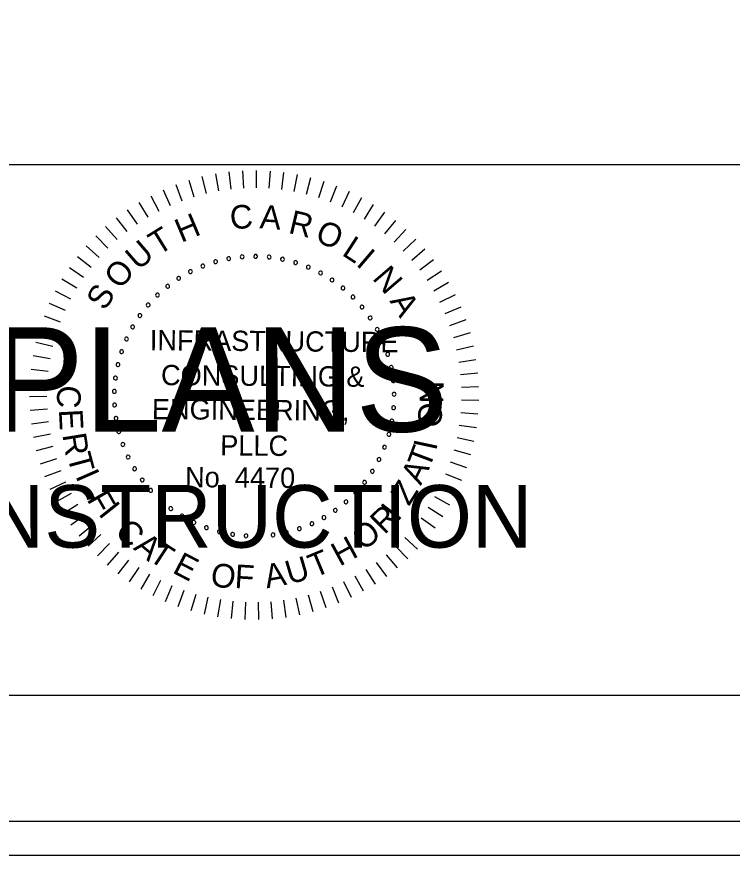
# Model space of a CAD drawing. Extents: x 967 to 1326, y 964 to 2864.
# Drawn here: x 1189.3 to 1212.88, y 963.72 to 991.36 of the extents above; entities that cross this region are included whole.
import ezdxf

# ---------------------------------------------------------------- set-up
doc = ezdxf.new("R2010")
doc.units = 0
for name, color, linetype in [('RD_PD_Final_TX', 7, 'Continuous'), ('RD_XS_TX_Elev_PR', 7, 'Continuous'), ('RD_XS_TX_Misc', 7, 'Continuous'), ('RD_XS_TX_ShdSlope', 7, 'Continuous')]:
    doc.layers.add(name, color=color, linetype=linetype)

msp = doc.modelspace()

# ---------------------------------------------------------------- linework, layer by layer
at = {"layer": 'RD_PD_Final_TX'}
for p, q in [((996.114, 986.486), (1323.886, 986.486)), ((1323.886, 968.983), (996.114, 968.983))]:
    msp.add_line(p, q, dxfattribs=at)
at = {"layer": 'RD_XS_TX_Elev_PR'}
for points in [[(967.409, 963.72), (1326.285, 963.72), (1326.285, 1183.72), (967.409, 1183.72)], [(988.525, 964.84), (1326.285, 964.84), (1326.285, 1182.6), (988.525, 1182.6)]]:
    msp.add_lwpolyline(points, close=True, dxfattribs=at)
at = {"layer": 'RD_XS_TX_ShdSlope'}
for p, q in [((1196.292, 986.245), (1196.357, 985.68)), ((1196.742, 986.282), (1196.772, 985.714)), ((1197.194, 986.292), (1197.189, 985.723)), ((1197.645, 986.274), (1197.606, 985.706)), ((1198.094, 986.228), (1198.02, 985.664)), ((1194.968, 985.971), (1195.134, 985.427)), ((1195.403, 986.09), (1195.536, 985.536)), ((1195.846, 986.181), (1195.945, 985.62)), ((1198.54, 986.156), (1198.432, 985.596)), ((1198.98, 986.056), (1198.838, 985.504)), ((1199.414, 985.929), (1199.238, 985.387)), ((1194.122, 985.656), (1194.353, 985.136)), ((1194.54, 985.827), (1194.739, 985.293)), ((1199.839, 985.777), (1199.63, 985.246)), ((1193.715, 985.461), (1193.978, 984.956)), ((1200.253, 985.598), (1200.013, 985.082)), ((1200.656, 985.395), (1200.385, 984.894)), ((1193.321, 985.241), (1193.614, 984.752)), ((1201.047, 985.167), (1200.745, 984.684)), ((1192.94, 984.997), (1193.263, 984.528)), ((1201.422, 984.917), (1201.092, 984.453)), ((1192.576, 984.731), (1192.926, 984.282)), ((1201.781, 984.643), (1201.424, 984.2)), ((1192.228, 984.443), (1192.605, 984.016)), ((1202.124, 984.349), (1201.739, 983.928)), ((1191.899, 984.134), (1192.301, 983.731)), ((1202.447, 984.034), (1202.038, 983.638)), ((1191.589, 983.805), (1192.015, 983.428)), ((1202.751, 983.7), (1202.318, 983.329)), ((1191.299, 983.459), (1191.748, 983.108)), ((1203.034, 983.348), (1202.579, 983.004)), ((1191.032, 983.095), (1191.501, 982.772)), ((1203.294, 982.979), (1202.82, 982.664)), ((1190.787, 982.716), (1191.274, 982.422)), ((1203.532, 982.595), (1203.04, 982.31)), ((1190.565, 982.323), (1191.07, 982.059)), ((1203.746, 982.198), (1203.237, 981.943)), ((1190.368, 981.916), (1190.888, 981.684)), ((1203.936, 981.788), (1203.412, 981.564)), ((1190.196, 981.499), (1190.729, 981.299)), ((1204.1, 981.367), (1203.563, 981.176)), ((1190.05, 981.072), (1190.594, 980.905)), ((1204.238, 980.937), (1203.691, 980.779)), ((1189.93, 980.636), (1190.484, 980.503)), ((1204.349, 980.5), (1203.794, 980.375)), ((1189.837, 980.195), (1190.398, 980.095)), ((1204.434, 980.056), (1203.872, 979.966)), ((1189.771, 979.748), (1190.337, 979.683)), ((1204.491, 979.608), (1203.925, 979.552)), ((1189.732, 979.298), (1190.301, 979.267)), ((1204.522, 979.158), (1203.953, 979.137)), ((1189.721, 978.847), (1190.29, 978.851)), ((1204.524, 978.706), (1203.955, 978.72)), ((1189.737, 978.396), (1190.306, 978.434)), ((1204.499, 978.256), (1203.932, 978.304)), ((1189.781, 977.946), (1190.346, 978.019)), ((1204.447, 977.807), (1203.884, 977.89)), ((1189.852, 977.5), (1190.412, 977.608)), ((1204.367, 977.363), (1203.81, 977.479)), ((1189.951, 977.06), (1190.502, 977.201)), ((1204.261, 976.924), (1203.712, 977.074)), ((1190.076, 976.626), (1190.617, 976.8)), ((1204.128, 976.492), (1203.589, 976.676)), ((1190.227, 976.2), (1190.757, 976.408)), ((1203.969, 976.07), (1203.442, 976.286)), ((1190.403, 975.785), (1190.92, 976.024)), ((1203.784, 975.658), (1203.271, 975.906)), ((1190.605, 975.381), (1191.106, 975.651)), ((1203.574, 975.258), (1203.078, 975.537)), ((1190.831, 974.99), (1191.315, 975.291)), ((1203.341, 974.871), (1202.862, 975.18)), ((1191.081, 974.614), (1191.545, 974.943)), ((1191.353, 974.253), (1191.796, 974.61)), ((1203.085, 974.5), (1202.626, 974.837)), ((1202.806, 974.145), (1202.368, 974.509)), ((1191.646, 973.91), (1192.067, 974.293)), ((1202.506, 973.807), (1202.092, 974.197)), ((1191.96, 973.585), (1192.356, 973.994)), ((1202.186, 973.488), (1201.796, 973.903)), ((1192.293, 973.28), (1192.664, 973.712)), ((1201.847, 973.19), (1201.484, 973.628)), ((1192.644, 972.996), (1192.988, 973.45)), ((1193.011, 972.734), (1193.327, 973.208)), ((1201.491, 972.912), (1201.155, 973.372)), ((1193.394, 972.495), (1193.68, 972.987)), ((1200.731, 972.425), (1200.453, 972.922)), ((1201.119, 972.657), (1200.811, 973.136)), ((1193.791, 972.279), (1194.047, 972.788)), ((1200.331, 972.217), (1200.083, 972.73)), ((1194.2, 972.088), (1194.424, 972.612)), ((1194.62, 971.923), (1194.812, 972.459)), ((1199.495, 971.877), (1199.312, 972.416)), ((1199.918, 972.034), (1199.702, 972.561)), ((1195.05, 971.783), (1195.208, 972.33)), ((1195.487, 971.67), (1195.612, 972.225)), ((1195.93, 971.584), (1196.021, 972.146)), ((1196.377, 971.524), (1196.434, 972.091)), ((1198.179, 971.562), (1198.097, 972.126)), ((1198.624, 971.64), (1198.508, 972.198)), ((1199.063, 971.745), (1198.913, 972.295)), ((1196.828, 971.493), (1196.85, 972.062)), ((1197.279, 971.488), (1197.267, 972.058)), ((1197.73, 971.512), (1197.683, 972.079))]:
    msp.add_line(p, q, dxfattribs=at)
for centre, start, end in [((1196.285, 983.388), 10.6038, 190.6038), ((1196.727, 983.447), 5.0653, 185.0653), ((1196.727, 983.447), 185.0653, 5.0653), ((1197.172, 983.464), 359.5268, 179.5268), ((1197.172, 983.464), 179.5268, 359.5268), ((1197.617, 983.438), 173.9884, 353.9884), ((1197.617, 983.438), 353.9884, 173.9884), ((1198.057, 983.369), 348.4499, 168.4499), ((1195.429, 983.142), 21.6807, 201.6807), ((1195.429, 983.142), 201.6807, 21.6807), ((1195.851, 983.285), 16.1422, 196.1422), ((1195.851, 983.285), 196.1422, 16.1422), ((1196.285, 983.388), 190.6038, 10.6038), ((1198.057, 983.369), 168.4499, 348.4499), ((1198.489, 983.258), 162.9114, 342.9114), ((1198.489, 983.258), 342.9114, 162.9114), ((1198.908, 983.106), 337.373, 157.373), ((1195.023, 982.958), 27.2191, 207.2191), ((1195.023, 982.958), 207.2191, 27.2191), ((1198.908, 983.106), 157.373, 337.373), ((1199.31, 982.914), 151.8345, 331.8345), ((1199.31, 982.914), 331.8345, 151.8345), ((1194.637, 982.736), 32.7576, 212.7576), ((1194.637, 982.736), 212.7576, 32.7576), ((1199.692, 982.684), 146.2961, 326.2961), ((1199.692, 982.684), 326.2961, 146.2961), ((1194.274, 982.478), 38.2961, 218.2961), ((1194.274, 982.478), 218.2961, 38.2961), ((1200.05, 982.419), 140.7576, 320.7576), ((1200.05, 982.419), 320.7576, 140.7576), ((1193.937, 982.186), 43.8345, 223.8345), ((1193.937, 982.186), 223.8345, 43.8345), ((1200.38, 982.12), 135.2191, 315.2191), ((1200.38, 982.12), 315.2191, 135.2191), ((1193.63, 981.862), 49.373, 229.373), ((1193.63, 981.862), 229.373, 49.373), ((1200.68, 981.79), 129.6807, 309.6807), ((1200.68, 981.79), 309.6807, 129.6807), ((1193.356, 981.511), 54.9114, 234.9114), ((1193.356, 981.511), 234.9114, 54.9114), ((1200.947, 981.433), 304.1422, 124.1422), ((1200.947, 981.433), 124.1422, 304.1422), ((1193.117, 981.135), 60.4499, 240.4499), ((1193.117, 981.135), 240.4499, 60.4499), ((1201.179, 981.052), 118.6038, 298.6038), ((1201.179, 981.052), 298.6038, 118.6038), ((1192.915, 980.737), 65.9884, 245.9884), ((1192.915, 980.737), 245.9884, 65.9884), ((1201.372, 980.651), 113.0653, 293.0653), ((1201.372, 980.651), 293.0653, 113.0653), ((1192.753, 980.322), 71.5268, 251.5268), ((1192.753, 980.322), 251.5268, 71.5268), ((1201.526, 980.233), 107.5268, 287.5268), ((1201.526, 980.233), 287.5268, 107.5268), ((1192.632, 979.894), 77.0653, 257.0653), ((1192.632, 979.894), 257.0653, 77.0653), ((1201.638, 979.801), 101.9884, 281.9884), ((1201.638, 979.801), 281.9884, 101.9884), ((1192.552, 979.455), 82.6038, 262.6038), ((1192.552, 979.455), 262.6038, 82.6038), ((1201.709, 979.361), 96.4499, 276.4499), ((1201.709, 979.361), 276.4499, 96.4499), ((1192.515, 979.011), 88.1422, 268.1422), ((1192.515, 979.011), 268.1422, 88.1422), ((1201.737, 978.917), 90.9114, 270.9114), ((1201.737, 978.917), 270.9114, 90.9114), ((1192.522, 978.565), 93.6807, 273.6807), ((1192.522, 978.565), 273.6807, 93.6807), ((1201.721, 978.471), 85.373, 265.373), ((1201.721, 978.471), 265.373, 85.373), ((1192.571, 978.122), 99.2191, 279.2191), ((1192.571, 978.122), 279.2191, 99.2191), ((1201.663, 978.029), 79.8345, 259.8345), ((1201.663, 978.029), 259.8345, 79.8345), ((1192.662, 977.686), 104.7576, 284.7576), ((1192.662, 977.686), 284.7576, 104.7576), ((1201.563, 977.595), 74.2961, 254.2961), ((1201.563, 977.595), 254.2961, 74.2961), ((1192.796, 977.261), 110.2961, 290.2961), ((1192.796, 977.261), 290.2961, 110.2961), ((1201.42, 977.173), 68.7576, 248.7576), ((1201.42, 977.173), 248.7576, 68.7576), ((1192.97, 976.851), 115.8345, 295.8345), ((1192.97, 976.851), 295.8345, 115.8345), ((1201.238, 976.766), 63.2191, 243.2191), ((1201.238, 976.766), 243.2191, 63.2191), ((1193.182, 976.459), 301.373, 121.373), ((1193.182, 976.459), 121.373, 301.373), ((1201.018, 976.379), 57.6807, 237.6807), ((1201.018, 976.379), 237.6807, 57.6807), ((1193.432, 976.09), 126.9114, 306.9114), ((1193.432, 976.09), 306.9114, 126.9114), ((1200.761, 976.014), 52.1422, 232.1422), ((1200.761, 976.014), 232.1422, 52.1422), ((1193.715, 975.746), 132.4499, 312.4499), ((1193.715, 975.746), 312.4499, 132.4499), ((1200.47, 975.677), 46.6038, 226.6038), ((1200.47, 975.677), 226.6038, 46.6038), ((1194.031, 975.431), 137.9884, 317.9884), ((1194.031, 975.431), 317.9884, 137.9884), ((1200.148, 975.369), 41.0653, 221.0653), ((1200.148, 975.369), 221.0653, 41.0653), ((1194.376, 975.149), 143.5268, 323.5268), ((1194.376, 975.149), 323.5268, 143.5268), ((1199.798, 975.093), 35.5268, 215.5268), ((1194.746, 974.901), 149.0653, 329.0653), ((1194.746, 974.901), 329.0653, 149.0653), ((1199.422, 974.853), 29.9884, 209.9884), ((1199.422, 974.853), 209.9884, 29.9884), ((1199.798, 975.093), 215.5268, 35.5268), ((1195.139, 974.69), 154.6038, 334.6038), ((1195.139, 974.69), 334.6038, 154.6038), ((1195.55, 974.517), 340.1422, 160.1422), ((1199.026, 974.65), 24.4499, 204.4499), ((1199.026, 974.65), 204.4499, 24.4499), ((1195.55, 974.517), 160.1422, 340.1422), ((1195.975, 974.386), 165.6807, 345.6807), ((1195.975, 974.386), 345.6807, 165.6807), ((1196.412, 974.295), 171.2191, 351.2191), ((1196.412, 974.295), 351.2191, 171.2191), ((1196.855, 974.248), 356.7576, 176.7576), ((1197.301, 974.243), 2.2961, 182.2961), ((1197.745, 974.282), 7.8345, 187.8345), ((1198.183, 974.363), 13.373, 193.373), ((1198.183, 974.363), 193.373, 13.373), ((1198.611, 974.486), 18.9114, 198.9114), ((1198.611, 974.486), 198.9114, 18.9114), ((1196.855, 974.248), 176.7576, 356.7576), ((1197.301, 974.243), 182.2961, 2.2961), ((1197.745, 974.282), 187.8345, 7.8345)]:
    msp.add_arc(centre, 0.0627, start, end, dxfattribs=at)

# ---------------------------------------------------------------- texts
at = {"layer": 'RD_XS_TX_Misc'}
for s, height, p in [('FINAL PLANS', 3.4375, (1174.145, 977.685)), ('NOT FOR CONSTRUCTION', 2.0625, (1170.901, 973.86))]:
    msp.add_text(s, height=height, dxfattribs=at).set_placement(p)
at = {"layer": 'RD_XS_TX_ShdSlope'}
for s, height, rotation, p in [('C', 0.78, 4.7281, (1196.355, 984.346)), ('A', 0.78, 355.6981, (1197.29, 984.39)), ('H', 0.78, 22.7882, (1194.72, 983.904)), ('R', 0.78, 346.6681, (1198.222, 984.238)), ('O', 0.78, 337.638, (1199.096, 983.972)), ('T', 0.78, 31.8182, (1193.961, 983.478)), ('U', 0.78, 40.8482, (1193.306, 982.976)), ('L', 0.78, 327.108, (1199.981, 983.52)), ('I', 0.78, 319.578, (1200.451, 983.182)), ('O', 0.78, 49.8782, (1192.707, 982.341)), ('N', 0.78, 310.548, (1200.994, 982.728)), ('S', 0.78, 58.9083, (1192.211, 981.642)), ('A', 0.78, 301.5179, (1201.576, 981.991)), ('INFRASTRUCTURE', 0.66873, 359.5268, (1193.682, 980.367)), ('CONSULTING &', 0.66873, 359.5268, (1194.051, 979.217)), ('N', 0.78, 89.2085, (1203.359, 978.604)), ('C', 0.78, 267.025, (1190.646, 979.227)), ('ENGINEERING,', 0.66873, 359.5268, (1193.751, 978.095)), ('O', 0.78, 83.2085, (1203.26, 977.786)), ('E', 0.78, 273.025, (1190.685, 978.408)), ('R', 0.78, 279.025, (1190.799, 977.583)), ('PLLC', 0.6687, 359.5268, (1196.002, 976.9)), ('I', 0.78, 77.9093, (1203.121, 977.032)), ('T', 0.78, 69.3954, (1202.891, 976.428)), ('T', 0.78, 285.025, (1190.955, 976.878)), ('No. 4470', 0.6687, 359.5268, (1194.843, 975.855)), ('A', 0.78, 63.3954, (1202.616, 975.888)), ('I', 0.78, 293.7713, (1191.221, 976.225)), ('Z', 0.78, 57.3954, (1202.224, 975.206)), ('F', 0.78, 299.7713, (1191.589, 975.455)), ('I', 0.78, 308.5268, (1191.965, 974.973)), ('R', 0.78, 44.5268, (1201.415, 974.267)), ('I', 0.78, 52.3339, (1201.856, 974.69)), ('C', 0.78, 314.5268, (1192.496, 974.346)), ('O', 0.78, 38.5268, (1200.73, 973.731)), ('A', 0.78, 320.5268, (1193.115, 973.822)), ('T', 0.78, 326.5268, (1193.602, 973.478)), ('H', 0.78, 28.5268, (1199.942, 973.23)), ('T', 0.78, 22.5268, (1199.108, 972.856)), ('E', 0.78, 332.5268, (1194.394, 973.051)), ('U', 0.78, 16.5268, (1198.288, 972.638)), ('O', 0.78, 350.5268, (1195.647, 972.614)), ('F', 0.78, 356.5268, (1196.465, 972.532)), ('A', 0.78, 10.5268, (1197.537, 972.517))]:
    msp.add_text(s, height=height, rotation=rotation, dxfattribs=at).set_placement(p)

doc.saveas('drawing.dxf')
